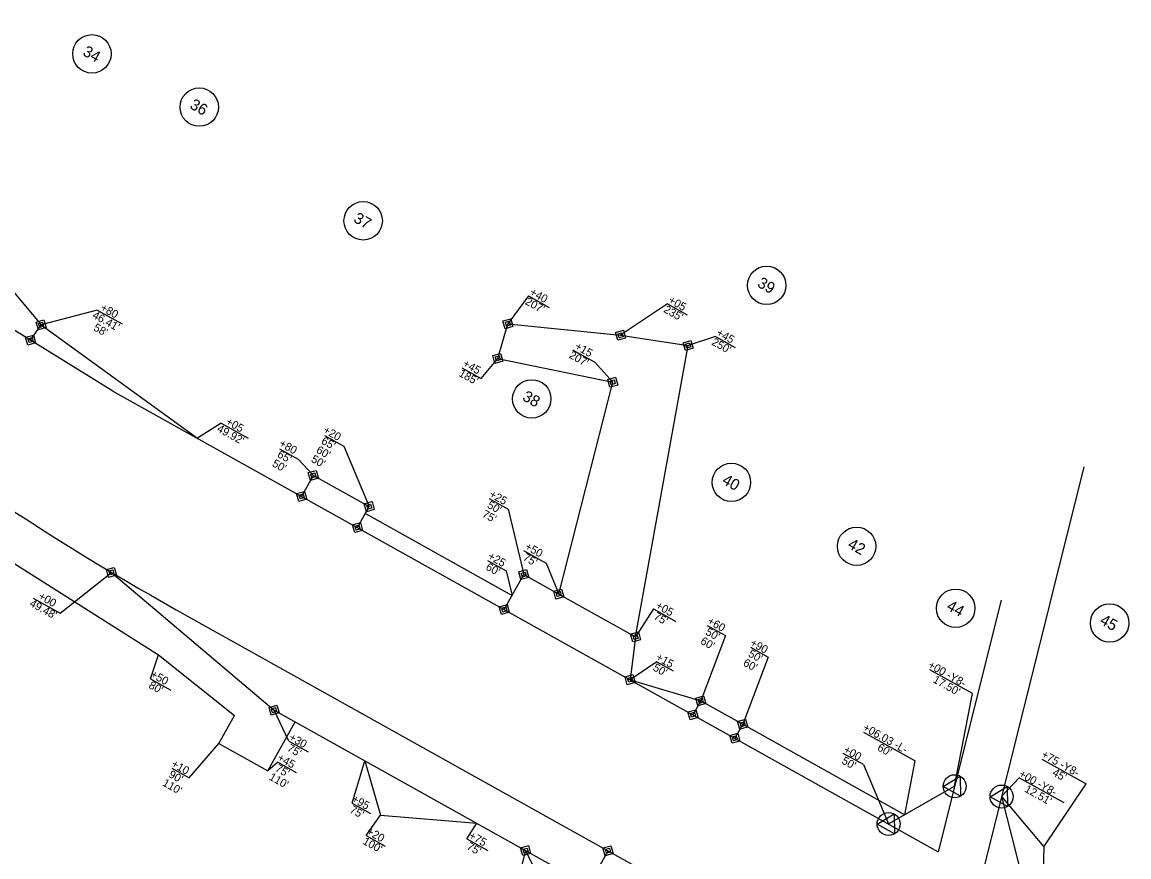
# Model space of a CAD drawing. Extents: x 1762160 to 1765875, y 710174 to 712931.
# Drawn here: x 1764467 to 1765159, y 710760 to 711281 of the extents above; entities that cross this region are included whole.
import ezdxf

# ---------------------------------------------------------------- set-up
doc = ezdxf.new("R2010")
doc.units = 0
for name, color, linetype in [('Exist Building', 7, 'Continuous'), ('Exist Building Foundations', 7, 'Continuous'), ('Exist Other Culture Area Outline', 7, 'Continuous'), ('Exist Other Culture Fence Line', 7, 'Continuous'), ('Exist Other Culture Located Object CELL', 7, 'Continuous'), ('Exist Other Culture Sign CELL', 7, 'Continuous'), ('Exist Roads Curbs', 7, 'Continuous'), ('Exist Roads EOP Other', 7, 'Continuous'), ('Exist Roads Soil', 7, 'Continuous'), ('Exist Structure Minor Head and End Wall', 7, 'Continuous'), ('Exist Utilities Other Pole CELL', 7, 'Continuous'), ('Exist Utilities Other Pole With Base CELL', 7, 'Continuous'), ('Exist Vegetation Shrub CELL', 7, 'Continuous'), ('Exist Vegetation Tree CELL', 7, 'Continuous'), ('Exist Vegetation Woods Line', 7, 'Continuous')]:
    doc.layers.add(name, color=color, linetype=linetype)

msp = doc.modelspace()

# ---------------------------------------------------------------- linework, layer by layer
at = {"layer": 'Exist Building'}
for p, q in [((1764891.55, 710857.52), (1764886.67, 710848.79)), ((1764891.55, 710857.52), (1764917.74, 710842.91)), ((1764917.74, 710842.91), (1764912.87, 710834.17))]:
    msp.add_line(p, q, dxfattribs=at)
at = {"layer": 'Exist Building Foundations'}
for p, q in [((1764764.69, 711071.43), (1764771.04, 711093.08)), ((1764771.04, 711093.08), (1764841.44, 711085.86)), ((1764841.44, 711085.86), (1764883.68, 711079.48)), ((1764850.82, 710897.42), (1764883.68, 711079.48)), ((1764764.69, 711071.43), (1764836.54, 711056.54)), ((1764802.79, 710924.21), (1764836.54, 711056.54)), ((1764642.15, 710985.2), (1764649.46, 710998.3)), ((1764649.46, 710998.3), (1764684.39, 710978.82)), ((1764677.08, 710965.72), (1764684.39, 710978.82)), ((1764782.11, 710763.99), (1764710.03, 710487.01))]:
    msp.add_line(p, q, dxfattribs=at)
at = {"layer": 'Exist Other Culture Area Outline'}
for p, q in [((1765008.93, 710780.58), (1765050.19, 710804.16)), ((1765079.51, 710797.73), (1765096.26, 710731.86))]:
    msp.add_line(p, q, dxfattribs=at)
at = {"layer": 'Exist Other Culture Fence Line'}
for p, q in [((1764783.92, 711110.45), (1764771.04, 711093.08)), ((1764783.92, 711110.45), (1764796.86, 711103.25)), ((1764870.77, 711105.42), (1764841.44, 711085.86)), ((1764870.77, 711105.42), (1764883.09, 711098.56)), ((1764900.67, 711085.1), (1764883.68, 711079.48)), ((1764900.67, 711085.1), (1764912.98, 711078.25)), ((1764754.24, 711058.92), (1764764.69, 711071.43)), ((1764811.38, 711076.84), (1764825.39, 711069.04)), ((1764742.22, 711065.61), (1764754.24, 711058.92)), ((1764825.39, 711069.04), (1764836.54, 711056.54)), ((1764656.36, 711023.34), (1764668.41, 711016.62)), ((1764668.41, 711016.62), (1764684.39, 710978.82)), ((1764628.26, 711014.99), (1764639.93, 711008.49)), ((1764649.46, 710998.3), (1764639.93, 711008.49)), ((1764791.34, 710745.57), (1764782.11, 710763.99))]:
    msp.add_line(p, q, dxfattribs=at)
at = {"layer": 'Exist Other Culture Located Object CELL'}
for p, q in [((1764591.85, 711031.01), (1764577.1, 711021.5)), ((1764591.85, 711031.01), (1764608.81, 711021.56)), ((1764758.29, 710945.2), (1764769.89, 710938.74)), ((1764769.89, 710938.74), (1764773.65, 710923.29)), ((1764547.62, 710871.31), (1764552.62, 710886.29)), ((1764547.62, 710871.31), (1764560.31, 710864.24)), ((1764993.14, 710838.03), (1765025.52, 710819.99)), ((1764571.85, 710809.47), (1764590.4, 710830.86)), ((1764561.01, 710815.51), (1764571.85, 710809.47)), ((1764627.28, 710819.11), (1764620.96, 710813.81)), ((1764627.28, 710819.11), (1764638.73, 710812.74)), ((1764673.68, 710793.63), (1764681.68, 710820.02)), ((1765019.07, 710786.38), (1765025.52, 710819.99)), ((1765104.62, 710821.15), (1765132.29, 710805.75)), ((1765105.88, 710766.35), (1765132.29, 710805.75)), ((1764673.68, 710793.63), (1764685.19, 710787.22)), ((1764682.42, 710773.34), (1764691.33, 710786)), ((1764745.42, 710771.24), (1764751.54, 710781.04)), ((1764682.42, 710773.34), (1764694.44, 710766.65)), ((1764745.42, 710771.24), (1764758.5, 710763.96))]:
    msp.add_line(p, q, dxfattribs=at)
at = {"layer": 'Exist Other Culture Sign CELL'}
for p, q in [((1764514.29, 711101.64), (1764479.37, 711092.4)), ((1764514.29, 711101.64), (1764529.95, 711092.92)), ((1764759.42, 710983.91), (1764771.28, 710977.3)), ((1764771.28, 710977.3), (1764780.96, 710936.39)), ((1764780.84, 710951.41), (1764794.85, 710943.61)), ((1764794.85, 710943.61), (1764802.79, 710924.21)), ((1764491.36, 710912.27), (1764523.31, 710937.75)), ((1764474.43, 710921.71), (1764491.36, 710912.27)), ((1764862.05, 710914.89), (1764850.82, 710897.42)), ((1764862.05, 710914.89), (1764876.06, 710907.09)), ((1764864.11, 710881.95), (1764847.38, 710870.71)), ((1764864.11, 710881.95), (1764874.28, 710876.29)), ((1764634.23, 710832.39), (1764624.92, 710851.68)), ((1764634.23, 710832.39), (1764646.22, 710825.71))]:
    msp.add_line(p, q, dxfattribs=at)
at = {"layer": 'Exist Roads Curbs'}
for p, q in [((1764479.37, 711092.4), (1764479.37, 711092.4)), ((1764771.04, 711093.08), (1764771.04, 711093.08)), ((1764841.44, 711085.86), (1764841.44, 711085.86)), ((1764472.8, 711082.85), (1764472.8, 711082.85)), ((1764883.68, 711079.48), (1764883.68, 711079.48)), ((1764764.69, 711071.43), (1764764.69, 711071.43)), ((1764836.54, 711056.54), (1764836.54, 711056.54)), ((1764649.46, 710998.3), (1764649.46, 710998.3)), ((1764642.15, 710985.2), (1764642.15, 710985.2)), ((1764684.39, 710978.82), (1764684.39, 710978.82)), ((1764677.08, 710965.72), (1764677.08, 710965.72)), ((1764523.31, 710937.75), (1764523.31, 710937.75)), ((1764780.96, 710936.39), (1764780.96, 710936.39)), ((1764802.79, 710924.21), (1764802.79, 710924.21)), ((1764768.78, 710914.56), (1764768.78, 710914.56)), ((1764850.82, 710897.42), (1764850.82, 710897.42)), ((1764847.38, 710870.71), (1764847.38, 710870.71)), ((1764891.55, 710857.52), (1764891.55, 710857.52)), ((1764624.92, 710851.68), (1764624.92, 710851.68)), ((1764886.67, 710848.79), (1764886.67, 710848.79)), ((1764917.74, 710842.91), (1764917.74, 710842.91)), ((1764912.87, 710834.17), (1764912.87, 710834.17)), ((1765050.19, 710804.16), (1765050.19, 710804.16)), ((1765079.51, 710797.73), (1765079.51, 710797.73)), ((1765008.93, 710780.58), (1765008.93, 710780.58)), ((1764782.11, 710763.99), (1764782.11, 710763.99)), ((1764833.59, 710763.9), (1764833.59, 710763.9))]:
    msp.add_line(p, q, dxfattribs=at)
for points in [[(1765042.98, 710804.05), (1765053.69, 710810.45), (1765053.9, 710797.97)], [(1765072.29, 710797.62), (1765083.01, 710804.02), (1765083.22, 710791.54)], [(1765001.72, 710780.48), (1765012.44, 710786.87), (1765012.64, 710774.4)]]:
    msp.add_lwpolyline(points, close=True, dxfattribs=at)
for centre in [(1765050.19, 710804.16), (1765079.51, 710797.73), (1765008.93, 710780.58)]:
    msp.add_circle(centre, 7.2, dxfattribs=at)
at = {"layer": 'Exist Roads EOP Other'}
for p, q in [((1764479.37, 711092.4), (1764577.1, 711021.5)), ((1764358.29, 711009.25), (1764552.62, 710886.29)), ((1764681.96, 710974.45), (1764773.65, 710923.29)), ((1764552.62, 710886.29), (1764600.14, 710848.33)), ((1764847.38, 710870.71), (1764891.55, 710857.52)), ((1764590.4, 710830.86), (1764600.14, 710848.33)), ((1764620.96, 710813.81), (1764638.02, 710844.38)), ((1764917.74, 710842.91), (1765019.07, 710786.38)), ((1764590.4, 710830.86), (1764620.96, 710813.81)), ((1765079.51, 710797.73), (1765105.88, 710766.35)), ((1764691.33, 710786), (1764751.54, 710781.04)), ((1765105.88, 710766.35), (1765105, 710726.99))]:
    msp.add_line(p, q, dxfattribs=at)
msp.add_lwpolyline([(1764681.68, 710820.02), (1764691.33, 710786)], dxfattribs=at)
at = {"layer": 'Exist Roads Soil'}
for p, q in [((1764462.19, 711112.99), (1764479.37, 711092.4)), ((1764472.8, 711082.85), (1764479.37, 711092.4)), ((1764523.31, 710937.75), (1764624.92, 710851.68)), ((1764768.78, 710914.56), (1764780.96, 710936.39)), ((1764780.96, 710936.39), (1764802.79, 710924.21)), ((1764802.79, 710924.21), (1764850.82, 710897.42)), ((1764850.82, 710897.42), (1764847.38, 710870.71)), ((1764624.92, 710851.68), (1764821.41, 710742.06)), ((1764821.41, 710742.06), (1764833.59, 710763.9))]:
    msp.add_line(p, q, dxfattribs=at)
at = {"layer": 'Exist Structure Minor Head and End Wall'}
for points in [[(1764476.23, 711094.15), (1764481.12, 711095.54), (1764482.52, 711090.65), (1764477.62, 711089.25)], [(1764477.8, 711093.27), (1764480.25, 711093.97), (1764480.94, 711091.52), (1764478.5, 711090.82)], [(1764767.89, 711094.83), (1764772.79, 711096.22), (1764774.18, 711091.33), (1764769.29, 711089.93)], [(1764769.47, 711093.96), (1764771.91, 711094.65), (1764772.61, 711092.2), (1764770.16, 711091.51)], [(1764469.66, 711084.6), (1764474.56, 711085.99), (1764475.95, 711081.09), (1764471.05, 711079.7)], [(1764838.3, 711087.62), (1764843.2, 711089.01), (1764844.59, 711084.11), (1764839.69, 711082.72)], [(1764839.87, 711086.74), (1764842.32, 711087.44), (1764843.02, 711084.99), (1764840.57, 711084.29)], [(1764471.23, 711083.72), (1764473.68, 711084.42), (1764474.38, 711081.97), (1764471.93, 711081.27)], [(1764880.54, 711081.23), (1764885.44, 711082.62), (1764886.83, 711077.72), (1764881.93, 711076.33)], [(1764882.11, 711080.35), (1764884.56, 711081.05), (1764885.26, 711078.6), (1764882.81, 711077.9)], [(1764761.54, 711073.18), (1764766.44, 711074.58), (1764767.83, 711069.68), (1764762.94, 711068.29)], [(1764763.11, 711072.31), (1764765.56, 711073), (1764766.26, 711070.56), (1764763.81, 711069.86)], [(1764833.39, 711058.29), (1764838.29, 711059.69), (1764839.68, 711054.79), (1764834.78, 711053.39)], [(1764834.96, 711057.42), (1764837.41, 711058.11), (1764838.11, 711055.66), (1764835.66, 711054.97)], [(1764646.31, 711000.06), (1764651.21, 711001.45), (1764652.6, 710996.55), (1764647.71, 710995.16)], [(1764647.89, 710999.18), (1764650.34, 710999.88), (1764651.03, 710997.43), (1764648.58, 710996.73)], [(1764639.01, 710986.96), (1764643.9, 710988.35), (1764645.3, 710983.45), (1764640.4, 710982.06)], [(1764640.58, 710986.08), (1764643.03, 710986.78), (1764643.72, 710984.33), (1764641.28, 710983.63)], [(1764681.25, 710980.57), (1764686.14, 710981.96), (1764687.54, 710977.07), (1764682.64, 710975.67)], [(1764682.82, 710979.69), (1764685.27, 710980.39), (1764685.96, 710977.94), (1764683.52, 710977.24)], [(1764673.94, 710967.47), (1764678.84, 710968.86), (1764680.23, 710963.97), (1764675.33, 710962.57)], [(1764675.51, 710966.59), (1764677.96, 710967.29), (1764678.66, 710964.84), (1764676.21, 710964.14)], [(1764520.16, 710939.5), (1764525.06, 710940.9), (1764526.45, 710936), (1764521.55, 710934.61)], [(1764521.73, 710938.63), (1764524.18, 710939.33), (1764524.88, 710936.88), (1764522.43, 710936.18)], [(1764777.81, 710938.14), (1764782.71, 710939.54), (1764784.1, 710934.64), (1764779.21, 710933.25)], [(1764779.39, 710937.27), (1764781.83, 710937.97), (1764782.53, 710935.52), (1764780.08, 710934.82)], [(1764799.65, 710925.97), (1764804.54, 710927.36), (1764805.94, 710922.46), (1764801.04, 710921.07)], [(1764801.22, 710925.09), (1764803.67, 710925.79), (1764804.36, 710923.34), (1764801.92, 710922.64)], [(1764765.63, 710916.31), (1764770.53, 710917.71), (1764771.92, 710912.81), (1764767.03, 710911.42)], [(1764767.21, 710915.44), (1764769.65, 710916.13), (1764770.35, 710913.69), (1764767.9, 710912.99)], [(1764847.68, 710899.17), (1764852.57, 710900.56), (1764853.97, 710895.67), (1764849.07, 710894.27)], [(1764849.25, 710898.29), (1764851.7, 710898.99), (1764852.39, 710896.54), (1764849.95, 710895.85)], [(1764844.23, 710872.47), (1764849.13, 710873.86), (1764850.52, 710868.96), (1764845.62, 710867.57)], [(1764845.8, 710871.59), (1764848.25, 710872.29), (1764848.95, 710869.84), (1764846.5, 710869.14)], [(1764888.4, 710859.27), (1764893.3, 710860.67), (1764894.69, 710855.77), (1764889.79, 710854.38)], [(1764889.97, 710858.4), (1764892.42, 710859.1), (1764893.12, 710856.65), (1764890.67, 710855.95)], [(1764621.77, 710853.43), (1764626.67, 710854.83), (1764628.06, 710849.93), (1764623.17, 710848.54)], [(1764623.34, 710852.56), (1764625.79, 710853.26), (1764626.49, 710850.81), (1764624.04, 710850.11)], [(1764883.53, 710850.54), (1764888.43, 710851.94), (1764889.82, 710847.04), (1764884.92, 710845.64)], [(1764885.1, 710849.67), (1764887.55, 710850.36), (1764888.25, 710847.91), (1764885.8, 710847.22)], [(1764914.6, 710844.66), (1764919.5, 710846.05), (1764920.89, 710841.16), (1764915.99, 710839.76)], [(1764916.17, 710843.78), (1764918.62, 710844.48), (1764919.32, 710842.03), (1764916.87, 710841.33)], [(1764909.73, 710835.93), (1764914.62, 710837.32), (1764916.02, 710832.42), (1764911.12, 710831.03)], [(1764911.3, 710835.05), (1764913.75, 710835.75), (1764914.44, 710833.3), (1764912, 710832.6)], [(1764783.86, 710767.13), (1764785.25, 710762.24), (1764780.36, 710760.84), (1764778.96, 710765.74)], [(1764835.34, 710767.04), (1764836.73, 710762.14), (1764831.84, 710760.75), (1764830.44, 710765.65)], [(1764782.99, 710765.56), (1764783.68, 710763.11), (1764781.23, 710762.42), (1764780.54, 710764.86)], [(1764834.46, 710765.47), (1764835.16, 710763.02), (1764832.71, 710762.32), (1764832.01, 710764.77)]]:
    msp.add_lwpolyline(points, close=True, dxfattribs=at)
at = {"layer": 'Exist Utilities Other Pole CELL'}
for p, q in [((1765061.35, 710862.08), (1765034.75, 710876.9)), ((1764993.18, 710817.65), (1764980.57, 710824.67)), ((1765118.61, 710793.73), (1765090.42, 710809.43))]:
    msp.add_line(p, q, dxfattribs=at)
for points in [[(1765050.19, 710804.16), (1765061.35, 710862.08)], [(1764993.18, 710817.65), (1765008.93, 710780.58)], [(1765079.51, 710797.73), (1765090.42, 710809.43)]]:
    msp.add_lwpolyline(points, dxfattribs=at)
at = {"layer": 'Exist Utilities Other Pole With Base CELL'}
for p, q in [((1764524.13, 711051.05), (1764458.64, 711091.62)), ((1764524.13, 711051.05), (1765039.97, 710763.27)), ((1765130.99, 711003.66), (1765067.11, 710748.13)), ((1765079.27, 710920.47), (1765039.97, 710763.27)), ((1764563.72, 710914.45), (1765126.44, 710600.52))]:
    msp.add_line(p, q, dxfattribs=at)
msp.add_arc((1765367.59, 712355.39), 1650, 220.60672, 240.8436, dxfattribs=at)
at = {"layer": 'Exist Vegetation Shrub CELL'}
for p, q in [((1764906.96, 710898.24), (1764891.55, 710857.52)), ((1764895.62, 710904.56), (1764906.96, 710898.24)), ((1764933.76, 710884.7), (1764917.74, 710842.91)), ((1764922.54, 710890.95), (1764933.76, 710884.7))]:
    msp.add_line(p, q, dxfattribs=at)
at = {"layer": 'Exist Vegetation Tree CELL'}
for centre in [(1764511.08, 711261.65), (1764578.17, 711228.39), (1764680.6, 711157.37), (1764932.75, 711117.04), (1764785.95, 711046.11), (1764910.71, 710993.96), (1764988.91, 710954.06), (1765050.82, 710915.34), (1765147.05, 710906.12)]:
    msp.add_circle(centre, 12, dxfattribs=at)

# ---------------------------------------------------------------- texts
at = {"layer": 'Exist Other Culture Fence Line'}
for s, rotation, p in [('+40', 330.89322, (1764784.25, 711111.37)), ("207'", 330.89322, (1764781.36, 711105.54)), ('+05', 330.89322, (1764870.84, 711106.36)), ("235'", 330.89322, (1764867.86, 711100.58)), ('+45', 330.89322, (1764900.85, 711086.01)), ('+15', 330.89322, (1764812.33, 711077.54)), ("250'", 330.89322, (1764897.87, 711080.23)), ("207'", 330.89322, (1764808.82, 711072.05)), ("185'", 330.89322, (1764739.89, 711060.7)), ('+45', 330.89322, (1764742.35, 711066.78)), ('+20', 330.88857, (1764655.1, 711025.24)), ('+80', 330.88857, (1764627.62, 711016.84)), ("60'", 330.88857, (1764650.78, 711012.77)), ("65'", 330.88857, (1764653.94, 711018.45)), ("65'", 330.88857, (1764626.46, 711010.05)), ("50'", 330.88857, (1764647.61, 711007.09)), ("50'", 330.88857, (1764623.29, 711004.37))]:
    msp.add_text(s, height=5, rotation=rotation, dxfattribs=at).set_placement(p)
at = {"layer": 'Exist Other Culture Located Object CELL'}
for s, rotation, p in [('+05', 330.88857, (1764594.32, 711030.49)), ("49.92'", 330.88857, (1764588.75, 711026.15)), ('+25', 330.89322, (1764758, 710946.47)), ("60'", 330.89322, (1764756.74, 710939.73)), ('+50', 330.88857, (1764547.27, 710872.64)), ("80'", 330.88857, (1764546.11, 710865.85)), ('+06.03 -L-', 330.88857, (1764992.33, 710839.4)), ("60'", 330.88857, (1765001.41, 710826.91)), ('+45', 330.88857, (1764626.45, 710820.61)), ('+75 -Y8-', 330.88857, (1765103.9, 710822.54)), ('+10', 330.88857, (1764560.28, 710816.66)), ("75'", 330.88857, (1764625.2, 710813.87)), ("110'", 330.88857, (1764554.74, 710804.86)), ("90'", 330.88857, (1764558.59, 710810.16)), ("110'", 330.88857, (1764621.35, 710808.57)), ("45'", 330.88857, (1765110.75, 710811.29)), ('+95', 330.88857, (1764672.96, 710794.84)), ("75'", 330.88857, (1764671.7, 710788.1)), ('+20', 330.88857, (1764682.26, 710774.53)), ('+75', 330.88857, (1764746.13, 710771.88)), ("100'", 330.88857, (1764679.89, 710768.41)), ("75'", 330.88857, (1764744.88, 710765.13))]:
    msp.add_text(s, height=5, rotation=rotation, dxfattribs=at).set_placement(p)
at = {"layer": 'Exist Other Culture Sign CELL'}
for s, p in [("46.41'", (1764510.97, 711097.01)), ('+80', (1764515.93, 711101.68)), ("58'", (1764511.61, 711089.21)), ("50'", (1764757.65, 710978.4)), ('+25', (1764758.91, 710985.14)), ("75'", (1764754.49, 710972.72)), ('+50', (1764781.17, 710952.45)), ("75'", (1764780.01, 710945.66)), ("49.48'", (1764471.7, 710917.01)), ('+00', (1764477.18, 710921.4)), ("75'", (1764861.66, 710908.85)), ('+05', (1764862.91, 710915.6)), ('+15', (1764863, 710883.31)), ("50'", (1764861.22, 710876.86)), ('+30', (1764633.78, 710833.3)), ("75'", (1764632.62, 710826.51))]:
    msp.add_text(s, height=5, rotation=330.89322, dxfattribs=at).set_placement(p)
at = {"layer": 'Exist Utilities Other Pole CELL'}
for s, p in [('+00 -Y8-', (1765033.12, 710878.47)), ("17.50'", (1765036.17, 710869.34)), ("50'", (1764979.14, 710818.69)), ('+00', (1764980.31, 710825.48)), ('+00 -Y8-', (1765089.83, 710810.42)), ("12.51'", (1765093.4, 710801))]:
    msp.add_text(s, height=5, rotation=330.88857, dxfattribs=at).set_placement(p)
at = {"layer": 'Exist Vegetation Shrub CELL'}
for s, p in [('+60', (1764895.21, 710905.93)), ("50'", (1764894.04, 710899.14)), ("60'", (1764890.88, 710893.46)), ('+90', (1764921.9, 710892.32)), ("50'", (1764920.74, 710885.53)), ("60'", (1764917.57, 710879.85))]:
    msp.add_text(s, height=5, rotation=330.89322, dxfattribs=at).set_placement(p)
at = {"layer": 'Exist Vegetation Woods Line'}
for s, p in [('34', (1764504.82, 711261.1)), ('36', (1764571.77, 711227.92)), ('37', (1764674.04, 711156.99)), ('39', (1764926.37, 711116.55)), ('38', (1764779.53, 711045.65)), ('40', (1764904.29, 710993.5)), ('42', (1764982.81, 710953.42)), ('44', (1765044.57, 710914.79)), ('45', (1765140.34, 710905.96))]:
    msp.add_text(s, height=7, rotation=330.88857, dxfattribs=at).set_placement(p)

doc.saveas('drawing.dxf')
